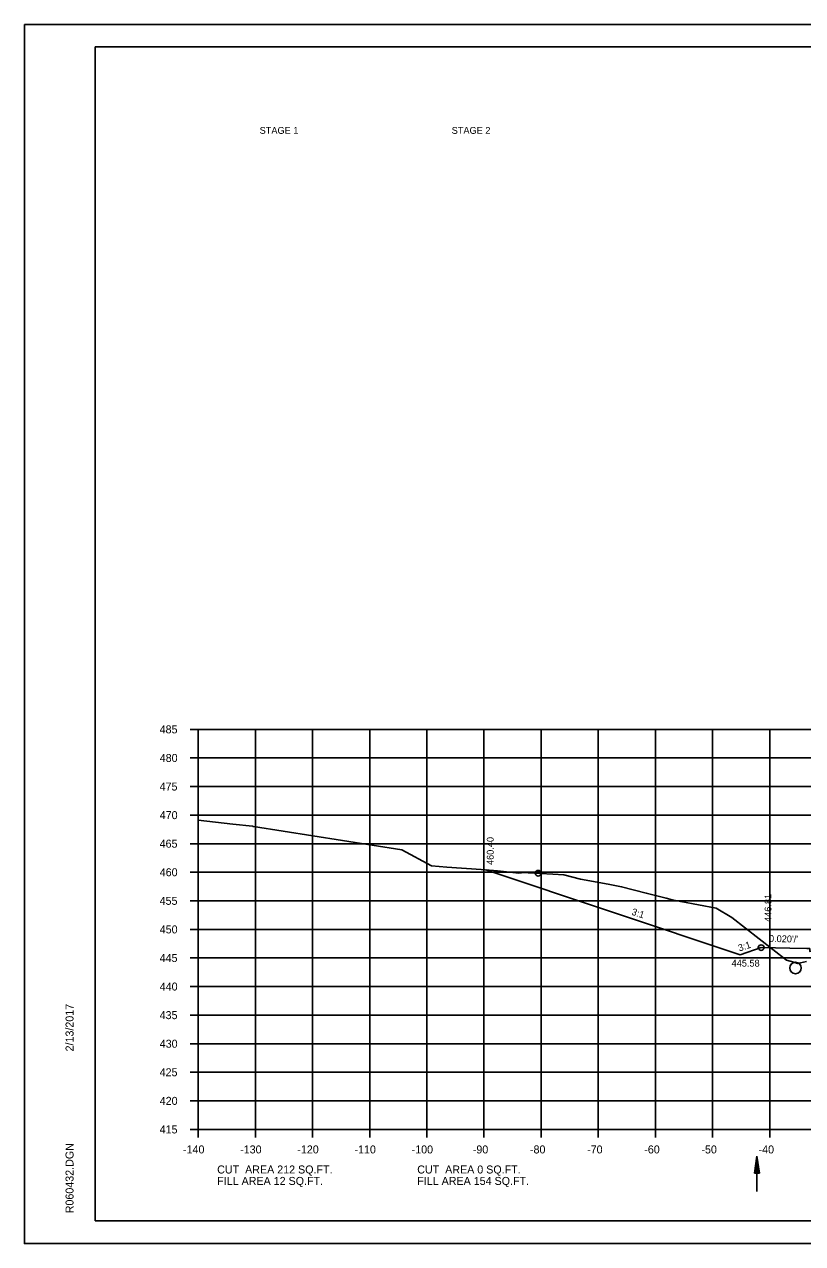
# Model space of a CAD drawing. Extents: x 1538688 to 1540766, y 656250 to 671912.
# Drawn here: x 1538687.8 to 1538823.9, y 667644.8 to 667858.1 of the extents above; entities that cross this region are included whole.
import ezdxf

# ---------------------------------------------------------------- set-up
doc = ezdxf.new("R2010")
doc.units = 0
for name, color, linetype in [('15', 7, 'Continuous'), ('18', 7, 'Continuous'), ('20', 7, 'Continuous'), ('22', 7, 'Continuous'), ('26', 7, 'Continuous'), ('39', 7, 'Continuous'), ('41', 7, 'Continuous'), ('42', 7, 'Continuous'), ('7', 7, 'Continuous'), ('Borings', 7, 'Continuous'), ('Default', 7, 'Continuous'), ('Horizontal Alignment', 7, 'Continuous'), ('RipRap', 7, 'Continuous')]:
    doc.layers.add(name, color=color, linetype=linetype)

msp = doc.modelspace()

# ---------------------------------------------------------------- linework, layer by layer
at = {"layer": '15'}
for p, q in [((1538815.48, 667657.13), (1538815.93, 667660.13)), ((1538815.55, 667657.13), (1538815.93, 667659.63)), ((1538816.38, 667657.13), (1538815.93, 667660.13)), ((1538816.3, 667657.13), (1538815.93, 667659.63)), ((1538815.48, 667657.13), (1538816.38, 667657.13)), ((1538815.63, 667657.13), (1538815.93, 667659.11)), ((1538815.7, 667657.13), (1538815.93, 667658.61)), ((1538815.78, 667657.13), (1538815.93, 667658.1)), ((1538815.86, 667657.13), (1538815.93, 667657.6)), ((1538816.23, 667657.13), (1538815.93, 667659.11)), ((1538816.15, 667657.13), (1538815.93, 667658.61)), ((1538816.08, 667657.13), (1538815.93, 667658.1)), ((1538816, 667657.13), (1538815.93, 667657.6))]:
    msp.add_line(p, q, dxfattribs=at)
at = {"layer": '18'}
msp.add_lwpolyline([(1538718.18, 667718.93), (1538724.23, 667718.22), (1538727.7, 667717.83), (1538727.73, 667717.83), (1538727.75, 667717.82), (1538727.84, 667717.81), (1538753.81, 667713.73), (1538758.98, 667710.93), (1538761.69, 667710.71), (1538767.71, 667710.26), (1538770.54, 667710.05), (1538774.27, 667709.66), (1538775.21, 667709.72), (1538775.91, 667709.69), (1538780.24, 667709.48), (1538782.14, 667709.36), (1538785.08, 667708.6), (1538789.93, 667707.69), (1538792.24, 667707.25), (1538796.58, 667706.16), (1538800.07, 667705.26), (1538801.12, 667704.98), (1538802.6, 667704.65), (1538808.77, 667703.48), (1538811.53, 667701.87), (1538821.08, 667694.4), (1538822.39, 667694.04), (1538823.02, 667693.83), (1538824.6, 667694.16)], dxfattribs=at)
at = {"layer": '20'}
msp.add_lwpolyline([(1538768.5, 667710.2), (1538812.98, 667695.37), (1538816.67, 667696.6), (1538821.67, 667696.5), (1538824.67, 667696.44), (1538825.17, 667696.44), (1538825.18, 667695.94), (1538826.18, 667695.96), (1538858.18, 667696.6), (1538890.18, 667695.96), (1538891.18, 667695.94), (1538891.19, 667696.44), (1538891.69, 667696.44), (1538894.69, 667696.5), (1538899.69, 667696.6), (1538910.25, 667693.08)], dxfattribs=at)
at = {"layer": '22'}
for p, q in [((1538718.18, 667734.79), (1538998.18, 667734.79)), ((1538718.18, 667664.79), (1538718.18, 667734.79)), ((1538718.18, 667734.79), (1538998.18, 667734.79)), ((1538718.18, 667664.79), (1538718.18, 667734.79)), ((1538728.18, 667664.79), (1538728.18, 667734.79)), ((1538728.18, 667664.79), (1538728.18, 667734.79)), ((1538738.18, 667664.79), (1538738.18, 667734.79)), ((1538738.18, 667664.79), (1538738.18, 667734.79)), ((1538748.18, 667664.79), (1538748.18, 667734.79)), ((1538748.18, 667664.79), (1538748.18, 667734.79)), ((1538758.18, 667664.79), (1538758.18, 667734.79)), ((1538758.18, 667664.79), (1538758.18, 667734.79)), ((1538768.18, 667664.79), (1538768.18, 667734.79)), ((1538768.18, 667664.79), (1538768.18, 667734.79)), ((1538778.18, 667664.79), (1538778.18, 667734.79)), ((1538778.18, 667664.79), (1538778.18, 667734.79)), ((1538788.18, 667664.79), (1538788.18, 667734.79)), ((1538788.18, 667664.79), (1538788.18, 667734.79)), ((1538798.18, 667664.79), (1538798.18, 667734.79)), ((1538798.18, 667664.79), (1538798.18, 667734.79)), ((1538808.18, 667664.79), (1538808.18, 667734.79)), ((1538808.18, 667664.79), (1538808.18, 667734.79)), ((1538818.18, 667664.79), (1538818.18, 667734.79)), ((1538818.18, 667664.79), (1538818.18, 667734.79)), ((1538718.18, 667729.79), (1538998.18, 667729.79)), ((1538718.18, 667729.79), (1538998.18, 667729.79)), ((1538718.18, 667724.79), (1538998.18, 667724.79)), ((1538718.18, 667724.79), (1538998.18, 667724.79)), ((1538718.18, 667719.79), (1538998.18, 667719.79)), ((1538718.18, 667719.79), (1538998.18, 667719.79)), ((1538718.18, 667714.79), (1538998.18, 667714.79)), ((1538718.18, 667714.79), (1538998.18, 667714.79)), ((1538718.18, 667709.79), (1538998.18, 667709.79)), ((1538718.18, 667709.79), (1538998.18, 667709.79)), ((1538718.18, 667704.79), (1538998.18, 667704.79)), ((1538718.18, 667704.79), (1538998.18, 667704.79)), ((1538718.18, 667699.79), (1538998.18, 667699.79)), ((1538718.18, 667699.79), (1538998.18, 667699.79)), ((1538718.18, 667694.79), (1538998.18, 667694.79)), ((1538718.18, 667694.79), (1538998.18, 667694.79)), ((1538718.18, 667689.79), (1538998.18, 667689.79)), ((1538718.18, 667689.79), (1538998.18, 667689.79)), ((1538718.18, 667684.79), (1538998.18, 667684.79)), ((1538718.18, 667684.79), (1538998.18, 667684.79)), ((1538718.18, 667679.79), (1538998.18, 667679.79)), ((1538718.18, 667679.79), (1538998.18, 667679.79)), ((1538718.18, 667674.79), (1538998.18, 667674.79)), ((1538718.18, 667674.79), (1538998.18, 667674.79)), ((1538718.18, 667669.79), (1538998.18, 667669.79)), ((1538718.18, 667669.79), (1538998.18, 667669.79)), ((1538718.18, 667664.79), (1538998.18, 667664.79)), ((1538718.18, 667664.79), (1538998.18, 667664.79))]:
    msp.add_line(p, q, dxfattribs=at)
at = {"layer": '26'}
for p, q in [((1538687.78, 667858.15), (1539021.11, 667858.15)), ((1538687.78, 667644.82), (1539021.11, 667644.82))]:
    msp.add_line(p, q, dxfattribs=at)
msp.add_lwpolyline([(1538687.77, 667858.15), (1539021.11, 667858.15), (1539021.11, 667644.81), (1538687.77, 667644.81)], close=True, dxfattribs=at)
for centre in [(1538777.66, 667709.61), (1538816.67, 667696.6)]:
    msp.add_circle(centre, 0.5, dxfattribs=at)
at = {"layer": '39'}
msp.add_line((1538815.93, 667653.94), (1538815.93, 667660.13), dxfattribs=at)
msp.add_circle((1538822.68, 667693.04), 1, dxfattribs=at)
at = {"layer": 'Borings'}
for p, q in [((1538716.78, 667734.79), (1538718.18, 667734.79)), ((1538718.18, 667664.79), (1538718.18, 667734.79)), ((1538716.78, 667729.79), (1538718.18, 667729.79)), ((1538716.78, 667724.79), (1538718.18, 667724.79)), ((1538716.78, 667719.79), (1538718.18, 667719.79)), ((1538716.78, 667714.79), (1538718.18, 667714.79)), ((1538716.78, 667709.79), (1538718.18, 667709.79)), ((1538716.78, 667704.79), (1538718.18, 667704.79)), ((1538716.78, 667699.79), (1538718.18, 667699.79)), ((1538716.78, 667694.79), (1538718.18, 667694.79)), ((1538716.78, 667689.79), (1538718.18, 667689.79)), ((1538716.78, 667684.79), (1538718.18, 667684.79)), ((1538716.78, 667679.79), (1538718.18, 667679.79)), ((1538716.78, 667674.79), (1538718.18, 667674.79)), ((1538716.78, 667669.79), (1538718.18, 667669.79)), ((1538716.78, 667664.79), (1538718.18, 667664.79)), ((1538718.18, 667664.79), (1538998.18, 667664.79)), ((1538718.18, 667663.39), (1538718.18, 667664.79)), ((1538728.18, 667663.39), (1538728.18, 667664.79)), ((1538738.18, 667663.39), (1538738.18, 667664.79)), ((1538748.18, 667663.39), (1538748.18, 667664.79)), ((1538758.18, 667663.39), (1538758.18, 667664.79)), ((1538768.18, 667663.39), (1538768.18, 667664.79)), ((1538778.18, 667663.39), (1538778.18, 667664.79)), ((1538788.18, 667663.39), (1538788.18, 667664.79)), ((1538798.18, 667663.39), (1538798.18, 667664.79)), ((1538808.18, 667663.39), (1538808.18, 667664.79)), ((1538818.18, 667663.39), (1538818.18, 667664.79))]:
    msp.add_line(p, q, dxfattribs=at)
at = {"layer": 'RipRap'}
for p, q in [((1538700.18, 667854.25), (1539016.36, 667854.25)), ((1538700.18, 667648.79), (1538700.18, 667854.25)), ((1538700.18, 667648.79), (1538700.18, 667648.79)), ((1539016.36, 667648.79), (1538700.18, 667648.79))]:
    msp.add_line(p, q, dxfattribs=at)

# ---------------------------------------------------------------- texts
at = {"layer": '41'}
for s, p in [('460.40', (1538769.87, 667711.06)), ('446.81', (1538818.47, 667701.1))]:
    msp.add_text(s, height=1.2, rotation=90, dxfattribs=at).set_placement(p)
at = {"layer": '42'}
for s, rotation, p in [('3:1', 341.5651, (1538793.9, 667702.39)), ('3:1', 18.4349, (1538812.87, 667695.92)), ("0.020'/'", 358.8542, (1538818.03, 667697.6))]:
    msp.add_text(s, height=1.2, rotation=rotation, dxfattribs=at).set_placement(p)
at = {"layer": '7'}
msp.add_text('445.58', height=1.2, dxfattribs=at).set_placement((1538811.5, 667693.28))
at = {"layer": 'Default'}
for s, p in [('STAGE 1', (1538728.93, 667839)), ('STAGE 2', (1538762.53, 667839))]:
    msp.add_text(s, height=1.2, dxfattribs=at).set_placement(p)
at = {"layer": 'Horizontal Alignment'}
for s, p in [('485', (1538711.43, 667734.09)), ('480', (1538711.45, 667729.09)), ('475', (1538711.43, 667724.09)), ('470', (1538711.45, 667719.09)), ('465', (1538711.43, 667714.09)), ('460', (1538711.45, 667709.09)), ('455', (1538711.43, 667704.09)), ('450', (1538711.45, 667699.09)), ('445', (1538711.43, 667694.09)), ('440', (1538711.45, 667689.09)), ('435', (1538711.43, 667684.09)), ('430', (1538711.45, 667679.09)), ('425', (1538711.43, 667674.09)), ('420', (1538711.45, 667669.09)), ('415', (1538711.43, 667664.09)), ('-140', (1538715.52, 667660.59)), ('-130', (1538725.52, 667660.59)), ('-120', (1538735.52, 667660.59)), ('-110', (1538745.52, 667660.59)), ('-100', (1538755.52, 667660.59)), ('-90', (1538766.22, 667660.59)), ('-80', (1538776.22, 667660.59)), ('-70', (1538786.22, 667660.59)), ('-60', (1538796.22, 667660.59)), ('-50', (1538806.22, 667660.59)), ('-40', (1538816.22, 667660.59)), ('CUT  AREA 212 SQ.FT.', (1538721.5, 667657.08)), ('CUT  AREA 0 SQ.FT.', (1538756.5, 667657.08)), ('FILL AREA 12 SQ.FT.', (1538721.5, 667655.08)), ('FILL AREA 154 SQ.FT.', (1538756.5, 667655.08))]:
    msp.add_text(s, height=1.4, dxfattribs=at).set_placement(p)
at = {"layer": 'RipRap'}
for s, p in [('2/13/2017', (1538696.37, 667678.44)), ('R060432.DGN', (1538696.37, 667650.12))]:
    msp.add_text(s, height=1.4, rotation=90, dxfattribs=at).set_placement(p)

doc.saveas('drawing.dxf')
